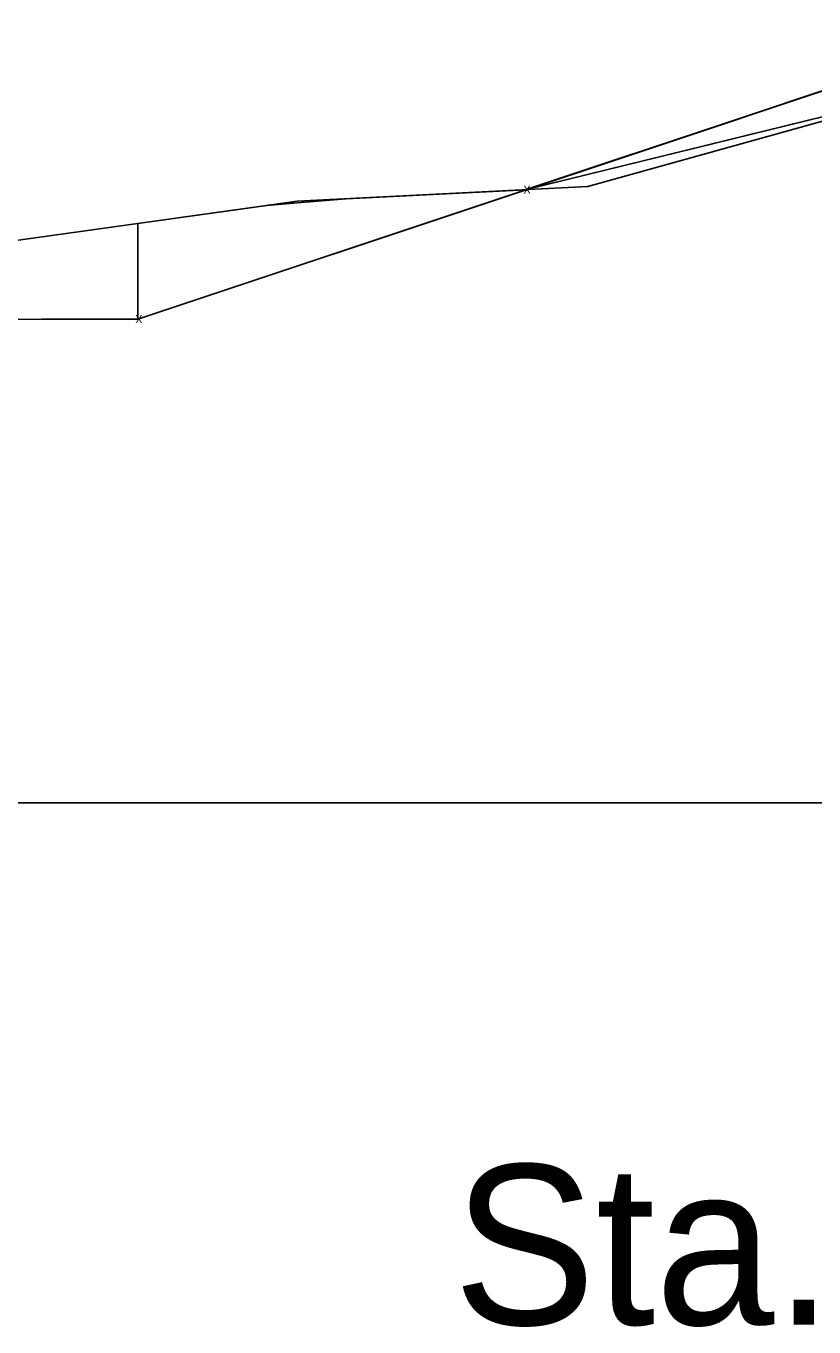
# Model space of a CAD drawing. Extents: x -26 to 303, y -16 to 6048.
# Drawn here: x 98.91 to 122.54, y 3484.28 to 3523.3 of the extents above; entities that cross this region are included whole.
import ezdxf

# ---------------------------------------------------------------- set-up
doc = ezdxf.new("R2010")
doc.units = 0
for name, color, linetype in [('CONST_DCH', 7, 'Continuous'), ('Draft_XS_Text', 7, 'Continuous'), ('DTM_P_FINISHED_GRADE2', 7, 'Continuous'), ('DTM_TEMP_DROP', 7, 'Continuous'), ('DTM_X_GROUND', 7, 'Continuous'), ('XS_CELL', 7, 'Continuous'), ('XS_M_SHAPES_EARTHWORK', 7, 'Continuous'), ('XS_P_GROUND', 7, 'Continuous'), ('XS_P_SUBGRADE_GRANULAR', 7, 'Continuous')]:
    doc.layers.add(name, color=color, linetype=linetype)

msp = doc.modelspace()

# ---------------------------------------------------------------- linework, layer by layer
at = {"layer": 'DTM_P_FINISHED_GRADE2'}
msp.add_lwpolyline([(113.908, 3518.388), (113.943, 3518.4), (126.768, 3522.675), (126.77, 3522.675), (134.577, 3522.987), (136.577, 3523.027), (150, 3523.296), (163.705, 3523.022), (163.707, 3523.022), (165.706, 3522.982), (165.707, 3522.982)], dxfattribs=at)
at = {"layer": 'DTM_X_GROUND'}
for points in [[(96.02, 3516.501), (102.4, 3517.392), (106.129, 3517.912), (107.037, 3517.989), (108.507, 3518.114), (113.908, 3518.388), (113.908, 3518.388), (113.942, 3518.396), (113.959, 3518.4), (126.975, 3521.598), (134.577, 3522.987), (134.577, 3522.987), (134.577, 3522.987), (136.577, 3523.027), (136.578, 3523.027), (150, 3523.296), (163.705, 3523.022), (163.707, 3523.022), (165.706, 3522.982), (165.707, 3522.982), (165.707, 3522.982), (170.73, 3522.431)], [(96.02, 3516.501), (102.4, 3517.392), (107.037, 3518.039), (115.756, 3518.481), (127.327, 3521.698), (129.588, 3521.745), (130.655, 3521.767), (132.204, 3521.843), (139.271, 3521.919), (150.5, 3522.03), (159.946, 3521.966), (171.035, 3521.93), (173.489, 3521.967), (174.598, 3521.727), (182.289, 3521.341), (183.914, 3521.26), (186.242, 3520.917), (195.662, 3520.649), (196.283, 3520.634), (205.45, 3520.374)]]:
    msp.add_lwpolyline(points, dxfattribs=at)
at = {"layer": 'XS_CELL'}
msp.add_line((0, 3500), (150, 3500), dxfattribs=at)
at = {"layer": 'XS_M_SHAPES_EARTHWORK'}
for points in [[(113.908, 3518.388), (113.942, 3518.396), (113.959, 3518.4), (126.824, 3521.561), (123.212, 3521.489)], [(102.263, 3514.506), (102.263, 3517.373), (102.4, 3517.392), (106.129, 3517.912), (107.037, 3517.989), (108.507, 3518.114), (113.908, 3518.388)]]:
    msp.add_lwpolyline(points, close=True, dxfattribs=at)
at = {"layer": 'XS_P_GROUND'}
for points in [[(126.77, 3522.675), (102.263, 3514.506)], [(113.908, 3518.388), (126.768, 3522.675), (126.77, 3522.675)], [(77.774, 3514.474), (79.005, 3514.482), (84.011, 3514.487), (84.099, 3514.487), (89.192, 3514.493), (94.285, 3514.498), (99.378, 3514.503), (102.263, 3514.506)]]:
    msp.add_lwpolyline(points, dxfattribs=at)

# ---------------------------------------------------------------- texts
at = {"layer": 'CONST_DCH'}
msp.add_text('X', height=0.24, dxfattribs=at).set_placement((102.185, 3514.386))
at = {"layer": 'Draft_XS_Text'}
msp.add_text('Sta. 165+00.0000 R1', height=4.8, dxfattribs=at).set_placement((111.716, 3484.35))
at = {"layer": 'DTM_TEMP_DROP'}
for p in [(113.829, 3518.268), (102.185, 3514.386)]:
    msp.add_text('X', height=0.24, dxfattribs=at).set_placement(p)
at = {"layer": 'XS_P_SUBGRADE_GRANULAR'}
msp.add_text('X', height=0.24, dxfattribs=at).set_placement((113.829, 3518.268))

doc.saveas('drawing.dxf')
